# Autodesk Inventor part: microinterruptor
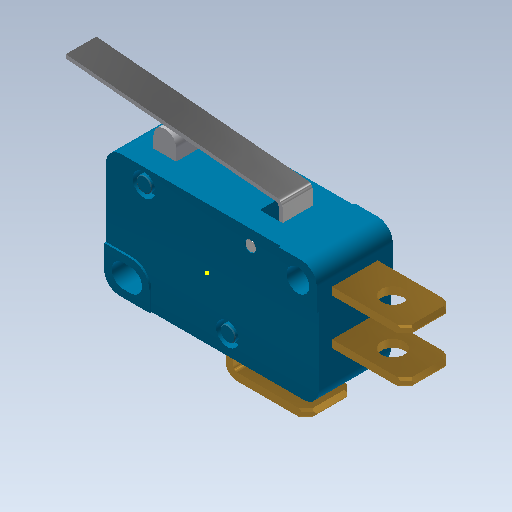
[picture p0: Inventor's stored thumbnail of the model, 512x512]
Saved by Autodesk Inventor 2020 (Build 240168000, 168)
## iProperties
Created: 2018-10
Part Number: microinterruptor
Material: Genérico
Document SubType Name: Modeling
Designer: Pedro
Density: 1 g/cm^3
Appearance: Por defecto
Author: Pedro
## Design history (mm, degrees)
sketch "Boceto1"
  geometry: L1 (-13.581, 7.66)-(14.419, 7.66); L2 (14.419, 7.66)-(14.419, -8.34); L3 (14.419, -8.34)-(-13.581, -8.34); L4 (-13.581, -8.34)-(-13.581, 7.66); L5 (-11.081, -7.34)-(-10.081, -7.34); L6 (-10.081, -4.34)-(-11.081, -4.34); C1 r 1.5 at (11.919, 5.16); A1 r 1.5 centre (-11.081, -5.84) between (-11.081, -4.34) and (-11.081, -7.34); A2 r 1.5 centre (-10.081, -5.84) between (-10.081, -7.34) and (-10.081, -4.34)
  constraints: 12 end point, 4 point on circle, 4 tangent, 3 centre point, 3 parallel, 1 horizontal, 1 perpendicular
extrude "Extrusión1" new body sketch "Boceto1" distance "d12" = 10; taper "d13" = 0 deg
sketch "Boceto2"
  geometry: L1 (0, 0)-(0, -10) reference; L2 (3.5, -3)-(6.5, -3); L3 (6.5, -3)-(6.5, -7); L4 (6.5, -7)-(3.5, -7); L5 (3.5, -7)-(3.5, -3); 1 further point
  constraints: 8 end point, 2 perpendicular, 1 parallel
extrude "Extrusión2" join sketch "Boceto2" distance "d19" = 3; taper "d20" = 0 deg
fillet "Empalme1" dims "d21" = 1.5
sketch "Boceto3"
  geometry: L1 (0, 10)-(28, 10) reference; L2 (25, 8)-(14, 8); L3 (14, 8)-(14, 2); L4 (14, 2)-(25, 2); L5 (25, 2)-(25, 8); 1 further point
  constraints: 8 end point, 3 perpendicular, 1 parallel
extrude "Extrusión3" join sketch "Boceto3" distance "d26" = 4; taper "d27" = 0 deg
sketch "Boceto4"
  geometry: L1 (0, 0)-(11, 0) reference; L2 (11, 0)-(11, -4) reference; L3 (11, -4)-(11, -3); L4 (11, -3)-(1, -3); L5 (1, -3)-(1, 0); L6 (11, 0)-(1, 0); L7 (11, 0)-(11, -3); 1 further point
  constraints: 10 end point, 2 collinear, 2 perpendicular, 2 point on line
extrude "Extrusión4" cut sketch "Boceto4" distance "d30" = 6; taper "d31" = 0 deg
fillet "Empalme2" dims "d32" = 0.5
fillet "Empalme3" dims "d33" = 1.5
chamfer "Chaflán1" distance "d34" = 1; stored, may be unused: second distance "d35" = 2, angle "d36" = 45 deg
hole "Hole1" diameter "d39" = 3; stored, may be unused: countersink angle "d43" = 90 deg, drill point angle "d45" = 118 deg; dims "d37" = 5, "d38" = 3, "d40" = 6, "d41" = 4, "d42" = 2, "d44" = 2
chamfer "Chaflán2" distance "d46" = 0.25; stored, may be unused: second distance "d47" = 2, angle "d48" = 45 deg
chamfer "Chaflán3" distance "d49" = 0.45; stored, may be unused: second distance "d50" = 2, angle "d51" = 45 deg
fillet "Empalme4" dims "d52" = 2
sketch "Boceto5"
  geometry: L1 (0, 16)-(0, 0) reference; L2 (-8, 6)-(-2, 6); L3 (-8, 13)-(-2, 13); L4 (-8, 6)-(-8, 7); L5 (-8, 7)-(-2, 7); L6 (-8, 13)-(-8, 12); L7 (-8, 12)-(-2, 12); L8 (-2, 6)-(-2, 7); L9 (-2, 12)-(-2, 13); 1 further point
  constraints: 16 end point, 9 perpendicular, 2 parallel
extrude "Extrusión5" join sketch "Boceto5" distance "d61" = 10; taper "d62" = 0 deg
hole "Hole2" diameter "d65" = 3; stored, may be unused: countersink angle "d69" = 90 deg, drill point angle "d71" = 118 deg; dims "d63" = 5, "d64" = 3, "d66" = 6, "d67" = 4, "d68" = 2, "d70" = 2
hole "Hole3" diameter "d74" = 3; stored, may be unused: countersink angle "d78" = 90 deg, drill point angle "d80" = 118 deg; dims "d72" = 5, "d73" = 3, "d75" = 6, "d76" = 4, "d77" = 2, "d79" = 2
chamfer "Chaflán4" distance "d81" = 1; stored, may be unused: second distance "d82" = 2, angle "d83" = 45 deg
chamfer "Chaflán5" distance "d84" = 0.25; stored, may be unused: second distance "d85" = 2, angle "d86" = 45 deg
chamfer "Chaflán6" distance "d87" = 0.45; stored, may be unused: second distance "d88" = 2, angle "d89" = 45 deg
fillet "Empalme5" dims "d90" = 2
sketch "Boceto6"
  geometry: L1 (-12.419, -8.34)-(11.581, -8.34) reference; L2 (13.581, -6.34)-(13.581, 5.66) reference; L3 (11.581, 7.66)-(-12.419, 7.66) reference; L4 (-14.419, 5.66)-(-14.419, -6.34) reference; L5 (10.081, -3.34)-(13.581, -3.34); L6 (7.581, -5.84)-(7.581, -8.34); L7 (-9.419, 5.16)-(-9.419, 7.66); L8 (-11.919, 2.66)-(-14.419, 2.66); C1 r 1.5 at (-11.919, 5.16) reference; A1 r 1.5 centre (10.081, -5.84) between (10.081, -4.34) and (10.081, -7.34) reference; A2 r 2 centre (-12.419, -6.34) between (-14.419, -6.34) and (-12.419, -8.34) reference; A3 r 2 centre (11.581, 5.66) between (13.581, 5.66) and (11.581, 7.66) reference; A4 r 2.5 centre (10.081, -5.84) between (10.081, -3.34) and (7.581, -5.84); A5 r 2.5 centre (-11.919, 5.16) between (-11.919, 2.66) and (-9.419, 5.16); 1 further point
  constraints: 8 end point, 5 tangent, 4 point on circle, 4 point on line, 3 perpendicular, 2 centre point, 2 coincident, 1 parallel
extrude "Extrusión6" cut sketch "Boceto6" distance "d93" = 0.25; taper "d94" = 0 deg
sketch "Boceto7"
  geometry: L1 (14.419, -6.34)-(14.419, 5.66) reference; L2 (12.419, 7.66)-(-11.581, 7.66) reference; L3 (-13.581, 5.66)-(-13.581, -6.34) reference; L4 (-11.581, -8.34)-(12.419, -8.34) reference; L5 (-10.081, -3.34)-(-13.581, -3.34); L6 (-7.581, -5.84)-(-7.581, -8.34); L7 (11.919, 2.66)-(14.419, 2.66); L8 (9.419, 5.16)-(9.419, 7.66); C1 r 1.5 at (11.919, 5.16) reference; A1 r 2 centre (12.419, -6.34) between (12.419, -8.34) and (14.419, -6.34) reference; A2 r 2 centre (-11.581, 5.66) between (-11.581, 7.66) and (-13.581, 5.66) reference; A3 r 1.5 centre (-10.081, -5.84) between (-10.081, -7.34) and (-10.081, -4.34) reference; A4 r 2.5 centre (11.919, 5.16) between (9.419, 5.16) and (11.919, 2.66); A5 r 2.5 centre (-10.081, -5.84) between (-7.581, -5.84) and (-10.081, -3.34); 1 further point
  constraints: 8 end point, 5 tangent, 4 perpendicular, 4 point on circle, 4 point on line, 2 centre point, 2 coincident
extrude "Extrusión7" cut sketch "Boceto7" distance "d95" = 0.25; taper "d96" = 0 deg
sketch "Boceto8"
  geometry: L1 (-5.5, 3)-(-5.5, 7); L2 (-5.5, 7)-(-8.5, 7); L3 (-8.5, 7)-(-8.5, 3); L4 (-8.5, 3)-(-5.5, 3); 1 further point
  constraints: 8 end point, 3 perpendicular
extrude "Extrusión8" cut sketch "Boceto8" distance "d101" = 4; taper "d102" = 0 deg
hole "Hole4" diameter "d105" = 1.5; stored, may be unused: countersink angle "d109" = 90 deg, drill point angle "d111" = 118 deg; dims "d103" = 19, "d104" = 2, "d106" = 6, "d107" = 4, "d108" = 2, "d110" = 2
sketch "Boceto9"
  geometry: L1 (-5.5, 7)-(-6, 7); L2 (-6, 7)-(-6, 3); L3 (-6, 3)-(-5.5, 3); L4 (-5.5, 3)-(-5.5, 7); 1 further point
  constraints: 8 end point, 2 parallel, 1 horizontal, 1 perpendicular
  dimensions: "d112" = 0.5 distance of L3.end L2.end; "d113" = 4 distance of L2.end L1.end
extrude "Extrusión9" join sketch "Boceto9" distance "d114" = 9; taper "d115" = 0 deg
sketch "Boceto10"
  geometry: L1 (0, 9)-(4, 9); L2 (4, 9)-(4, 6); L3 (4, 6)-(0, 6); L4 (0, 6)-(0, 9); 1 further point
  constraints: 8 end point, 2 parallel, 1 horizontal, 1 perpendicular
  dimensions: "d116" = 4 distance of L2.end L3.end; "d117" = 3 distance of L1.end L2.end
extrude "Extrusión10" join sketch "Boceto10" distance "d118" = 28; taper "d119" = 0 deg
sketch "Boceto11"
  geometry: L1 (-11.5, 2)-(-11.5, 5) reference; L2 (0.086, 2)-(-11.5, 2) reference; L3 (3, 0)-(3, 1.5) reference; L4 (16.5, 2)-(2.914, 2) reference; L5 (-11.5, 4.5)-(16.5, 2); L6 (16.5, 2)-(2.914, 2); L7 (0.086, 2)-(-11.5, 2); L8 (-11.5, 4.5)-(-11.5, 2); A1 r 1.5 centre (1.5, 1.5) between (3, 1.5) and (2.914, 2) reference; A2 r 1.5 centre (1.5, 1.5) between (2.914, 2) and (0.086, 2); 1 further point
  constraints: 9 end point, 3 collinear, 3 point on line, 2 point on circle, 1 centre point, 1 coincident
extrude "Extrusión11" cut sketch "Boceto11" distance "d121" = 4; taper "d122" = 0 deg
sketch "Boceto12"
  geometry: L1 (0, 0)-(0, 5) reference; L2 (-28.5, 5)-(0, 5); L3 (-28.5, 5)-(0, 2.455); L4 (0, 5)-(0, 2.455); 1 further point
  constraints: 6 end point, 1 perpendicular
extrude "Extrusión12" cut sketch "Boceto12" distance "d124" = 4; taper "d125" = 0 deg
fillet "Empalme6" dims "d126" = 0.5
fillet "Empalme7" dims "d127" = 0.8
sketch "Boceto13"
  geometry: C1 r 1.5 at (-8.581, 5.66); C2 r 1 at (-8.581, 5.66); C3 r 1.5 at (2.419, -5.84); C4 r 1 at (2.419, -5.84); 1 further point
  constraints: 4 centre point, 2 coincident
extrude "Extrusión13" cut sketch "Boceto13" distance "d134" = 1; taper "d135" = 0 deg
sketch "Boceto14"
  geometry: C1 r 0.75 at (-5.419, 5.66) reference; C2 r 0.7 at (-5.419, 5.66); 1 further point
  constraints: 1 centre point, 1 coincident
  dimensions: "d136" = 1.4 diameter of C2
extrude "Extrusión14" join sketch "Boceto14" distance "d137" = 9.5; taper "d138" = 0 deg
fillet "Empalme8" dims "d139" = 0.1
fillet "Empalme9" dims "d140" = 0.1
chamfer "Chaflán7" distance "d141" = 0.1; stored, may be unused: second distance "d142" = 2, angle "d143" = 45 deg
fillet "Empalme10" dims "d144" = 0.1
sketch "Boceto15"
  geometry: 1 further point
node "Sólido1"
